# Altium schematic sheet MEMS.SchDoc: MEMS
size A4; Date: Not used; ApprovedBy: Not used; CheckedBy: Not used; Author: Not used; CompanyName: STMicroelectronics; DrawnBy: Not used; Engineer: Not used; Organization: Not used; Address1: Not used; Address2: Not used; Address3: Not used; Address4: Not used; DocumentNumber: Not used; Revision: Not used; SheetNumber: 12; SheetTotal: 16
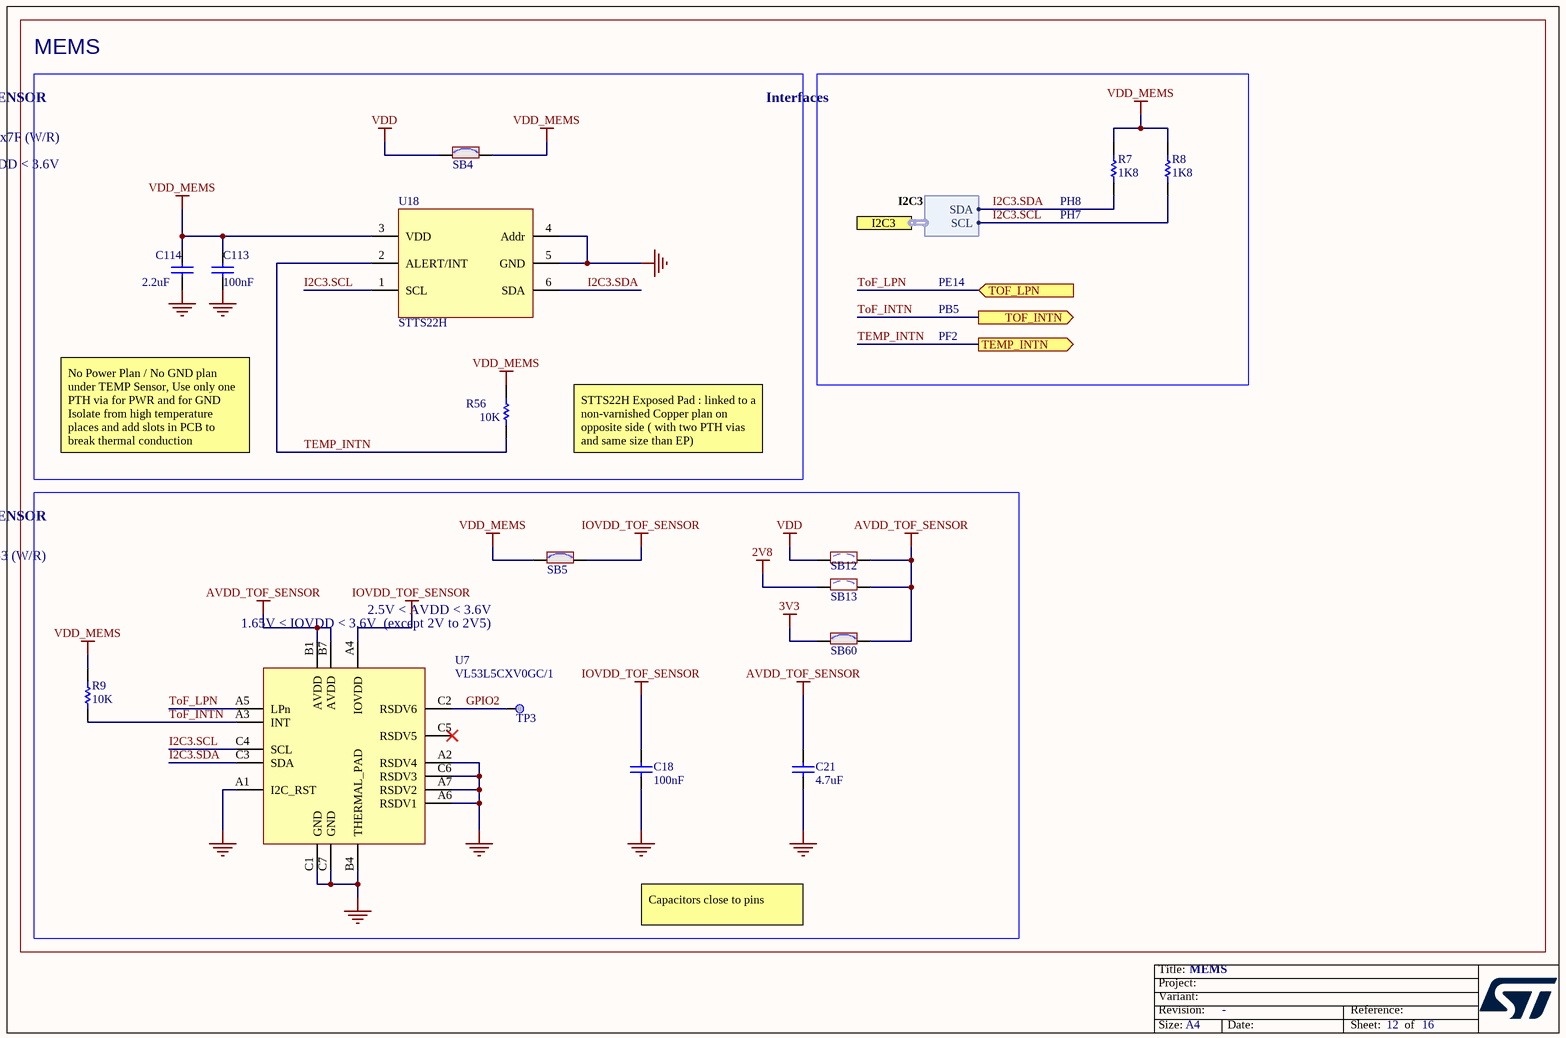
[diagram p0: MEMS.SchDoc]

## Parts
C18  value 100nF  [C0603]  (hidden comment: Capacitor)
C21  value 4.7uF  [C0603_H0P8]  (hidden comment: Capacitor)
C113  value 100nF  [C0603]  (hidden comment: Capacitor)
C114  value 2.2uF  [C0603]  (hidden comment: Capacitor)
R7  value 1K8  [R0402]  (hidden comment: Resistor)
R8  value 1K8  [R0402]  (hidden comment: Resistor)
R9  value 10K  [R0603]  (hidden comment: Resistor)
R56  value 10K  [R0603]  (hidden comment: Resistor)
SB4  SB_ON  [SOLDER-BRIDGE_R0402-0R]  (value not drawn)
SB5  SB_ON  [SOLDER-BRIDGE_R0402-0R]  (value not drawn)
SB12  SB_OFF  [SOLDER-BRIDGE_R0402-0R]  (value not drawn)
SB13  SB_OFF  [SOLDER-BRIDGE_R0402-0R]  (value not drawn)
SB60  SB_ON  [SOLDER-BRIDGE_R0402-0R]  (value not drawn)
TP3  Test Point  [TP_SMD_1MM]  (value not drawn)  (no BOM)
U7  VL53L5CXV0GC/1  [ICC_LGA16_6P4X3_P075_H1P5]
U18  STTS22H  [ICC_UDFN6-EPAD_2X2_P065]

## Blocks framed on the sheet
MEMS: C113 C114 R56 SB4 U18
Interfaces: R7 R8
TIME OF FLIGHT SENSOR: C18 C21 R9 SB5 SB12 SB13 SB60 TP3 U7

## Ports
I2C3 (harness I2C3), TEMP_INTN (out), TOF_INTN (out), TOF_LPN (in)

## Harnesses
I2C3: SDA, SCL

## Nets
2V8: SB13.1
3V3: SB60.1
AVDD_TOF_SENSOR: C21.2 SB12.2 SB13.2 SB60.2 U7.B1(AVDD) U7.B7(AVDD)
GND: C18.2 C21.1 C113.2 C114.1 U7.A1(I2C_RST) U7.A2(RSDV4) U7.A6(RSDV1) U7.A7(RSDV2) U7.B4(THERMAL_PAD) U7.C1(GND) U7.C6(RSDV3) U7.C7(GND) U18.4(Addr) U18.5(GND)
IOVDD_TOF_SENSOR: C18.1 SB5.2 U7.A4(IOVDD)
VDD: SB4.1 SB12.1
VDD_MEMS: C113.1 C114.2 R7.2 R8.2 R9.2 R56.2 SB4.2 SB5.1 U18.3(VDD)
GPIO2: TP3.1 U7.C2(RSDV6)
I2C3.SCL: R8.1 U7.C4(SCL) U18.1(SCL) ; port I2C3.SCL
I2C3.SDA: R7.1 U7.C3(SDA) U18.6(SDA) ; port I2C3.SDA
TEMP_INTN: R56.1 U18.2(ALERT/INT) ; port TEMP_INTN
ToF_INTN: R9.1 U7.A3(INT) ; port TOF_INTN
ToF_LPN: U7.A5(LPn) ; port TOF_LPN

Not connected (* = marked no-connect by the designer): U7 C5(RSDV5)*

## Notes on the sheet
- TEMPERATURE SENSOR
- 1.5V < VDD < 3.6V
- I2C Default address : 0x7E / 0x7F (W/R)
- (near R7) PH7
- (near R7) PH8
- PE14
- PB5
- PF2
- No Power Plan / No GND plan under TEMP Sensor, Use only one PTH via for PWR and for GND
  Isolate from high temperature places and add slots in PCB to break thermal conduction
- STTS22H Exposed Pad : linked to a non-varnished Copper plan on opposite side ( with two PTH vias and same size than EP)
- I2C Default address : 0x52 / 0x53 (W/R)
- 1.65V < IOVDD < 3.6V  (except 2V to 2V5)
- (near SB5) 2.5V < AVDD < 3.6V
- Capacitors close to pins

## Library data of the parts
C18 C113 = MCD-00211: Capacitor, MLCC, 100nF, 16V, X7R, +/-10%, 0603, T=0.8mm; Manufacturer_Part_Number: CC0603KRX7R7BB104; Manufacturer: YAGEO; Part_Preference: Recommended; Order_Code_RS: 669-8763
C21 = MCD-01721: Capacitor, MLCC, 4.7uF, 10V, X5R, +/-10%, 0603, T=0.8mm; Part_Preference: Recommended; Manufacturer: YAGEO; Manufacturer_Part_Number: CC0603KRX5R6BB475
C114 = MCD-00012: Capacitor, MLCC, 2.2uF, 10V, X5R, +/- 10%, 0603, T=0.8mm; BMS_Part_Number: 9142010; Part_Preference: Recommended; Manufacturer: YAGEO; Manufacturer_Part_Number: CC0603KRX5R6BB225; Alternate_Manufacturer: KEMET; Alternate_Manufacturer_Part_Number: C0603C225K8PACTU
R7 R8 = MCD-00409: Resistor, 1K8, 0402, +/-1%, 1/16W; Manufacturer_Part_Number: RC0402FR-071K8L; Manufacturer: YAGEO; Part_Preference: Recommended; Component_Country_Of_Origin: China
R9 R56 = MCD-00220: Resistor, 10K, 0603, +/-1%, 1/10W; Manufacturer_Part_Number: RC0603FR-0710KL; Manufacturer: YAGEO; Part_Preference: Recommended
SB4 SB5 SB60 = MCD-01618: Solder Bridge 0402 ON; Part_Type: Misc; Manufacturer_Part_Number: RC0402JR-070RL; Manufacturer: YAGEO; Part_Preference: Recommended; Order_Code_RS: 618-5804; Component_Country_Of_Origin: China
SB12 = MCD-02162: Solder Bridge 0402 OFF; Part_Type: Misc; Manufacturer_Part_Number: RC0402JR-070RL; Manufacturer: YAGEO; Part_Preference: Recommended; Order_Code_RS: 618-5804; Component_Country_Of_Origin: China
SB13 = MCD-02162: Solder Bridge 0402 OFF; Part_Type: Misc; Manufacturer_Part_Number: RC0402JR-070RL; Manufacturer: YAGEO; Part_Preference: Recommended; Order_Code_RS: 618-5804; Component_Country_Of_Origin: China; ShowFields: YES; ID: 4262
TP3 = MCD-00074: Test Point 1mm; Part_Type: Misc; Part_Preference: Recommended
U7 = MCD-02590: Time-of-Flight 8x8 multizone ranging sensor with wide field of view; Part_Type: IC; Part_Preference: Recommended; Manufacturer: STMICROELECTRONICS; ShowFields: YES; ID: 4696
U18 = MCD-02159: temperature sensor; Part_Type: IC; Part_Preference: Recommended; Manufacturer: STMICROELECTRONICS; Manufacturer_HQ_COO: EU; Order_code_RS: 194-7646; Component_Country_Of_Origin: Thailand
